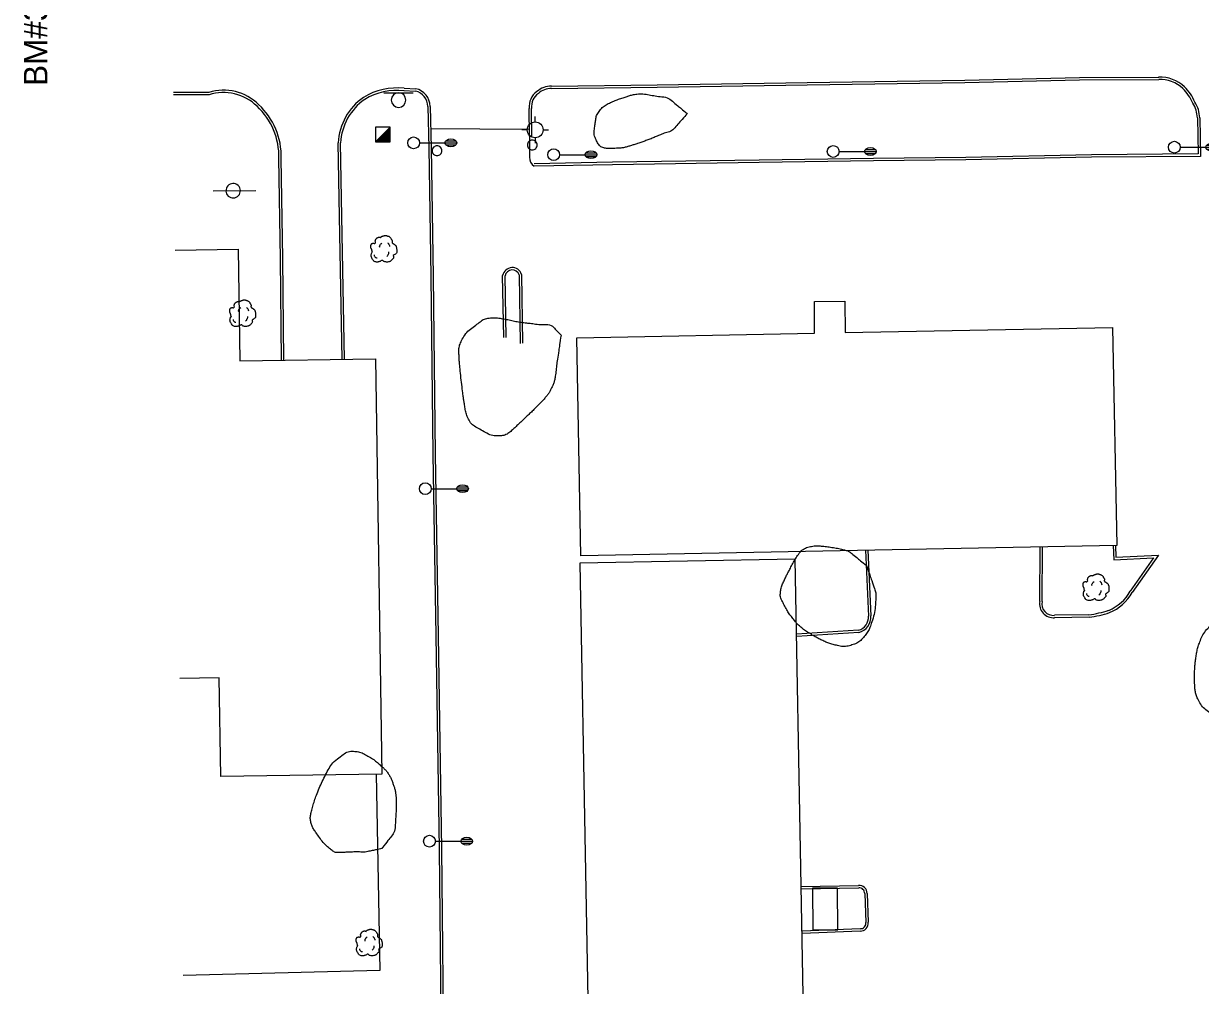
# Model space of a CAD drawing. Extents: x 2145380 to 2157287, y 139568 to 149130.
# Drawn here: x 2150211 to 2150511, y 140080.8 to 140325.9 of the extents above; entities that cross this region are included whole.
import ezdxf

# ---------------------------------------------------------------- set-up
doc = ezdxf.new("R2010")
doc.units = 0
for name, color, linetype in [('SURV_Benchmark', 7, 'Continuous'), ('TOPO_Asphalt', 7, 'Continuous'), ('TOPO_Building', 7, 'Continuous'), ('TOPO_Curb Back', 7, 'Continuous'), ('TOPO_Fence', 7, 'Continuous'), ('TOPO_Light Pole', 7, 'Continuous'), ('TOPO_Misc', 7, 'Continuous'), ('TOPO_Sign', 7, 'Continuous'), ('TOPO_Tree', 7, 'Continuous'), ('TOPO_Tree Line', 7, 'Continuous'), ('TOPO_Water Fire Hydrant', 7, 'Continuous')]:
    doc.layers.add(name, color=color, linetype=linetype)

# ---------------------------------------------------------------- blocks, each defined once
blk = doc.blocks.new('LP')
at = {"layer": 'TOPO_Light Pole'}
blk.add_line((3.81, 0), (20.32, 0), dxfattribs=at)
for points in [[(20.32, 0), (27.94, 0)], [(20.32, 0), (23.5, 0)], [(20.83, 1.27), (27.43, 1.27)], [(20.83, 1.27), (23.5, 1.27)], [(23.71, 1.27), (27.43, 1.27)], [(23.71, 0), (27.94, 0)], [(20.83, -1.27), (27.43, -1.27)], [(20.83, -1.27), (23.5, -1.27)], [(23.71, -1.27), (27.43, -1.27)]]:
    blk.add_lwpolyline(points, dxfattribs=at)
blk.add_circle((0, 0), 3.81, dxfattribs=at)
blk.add_ellipse((24.13, 0), major_axis=(3.81, 0), ratio=0.666667, dxfattribs=at)
blk = doc.blocks.new('FIRHYD')
at = {"layer": 'TOPO_Water Fire Hydrant'}
for p, q in [((0, 10.2), (0, 17.3)), ((10.2, 0), (17.3, 0)), ((-10.2, 0), (-17.3, 0)), ((0, -10.2), (0, -17.3))]:
    blk.add_line(p, q, dxfattribs=at)
blk.add_circle((0, 0), 10.2, dxfattribs=at)
blk = doc.blocks.new('POST')
at = {"layer": 'TOPO_Misc'}
for start, end in [(89.99996, 180.00004), (179.99996, 270.00004), (359.99996, 90.00004), (269.99996, 0.00004)]:
    blk.add_arc((-0.01, 0.03), 3.16, start, end, dxfattribs=at)
blk = doc.blocks.new('TREE')
at = {"layer": 'TOPO_Tree'}
for points in [[(-14.1, -0.4), (-14.2, 0.5), (-14.4, 1.4), (-14.6, 2.3), (-14.8, 3.2), (-15.5, 4), (-15.7, 4.9), (-15.8, 5.6), (-15.7, 6.3), (-15.7, 7), (-15.6, 7.9), (-15.7, 8.8), (-15.1, 9.7), (-14.6, 10.4), (-13.8, 10.5), (-13, 10.7), (-12.2, 11), (-11.1, 10), (-10.4, 10.7), (-9.4, 11.7), (-10.3, 13.3), (-9.8, 14.4), (-9.6, 15.1), (-9.3, 15.9), (-8.8, 16.5), (-8.2, 17.3), (-7.5, 17.7), (-6.7, 18.1), (-6.1, 18.4), (-5.6, 18.6), (-5.1, 18.7), (-4.5, 18.7), (-4, 18.5), (-3.5, 18.1)], [(-3.5, 17.6), (-3.1, 18.3), (-2.6, 18.8), (-1.9, 19.2), (-1, 19.7), (-0.2, 20), (0.7, 20.2), (1.6, 20.5), (2.5, 20.8), (3.4, 20.8), (4.1, 20.7), (4.8, 20.5), (5.5, 20.2), (6.4, 19.9), (7.3, 19.7), (8.2, 19.2), (9.4, 18.4), (10, 17.2), (10.8, 16), (11.2, 15.3), (11.6, 14.6), (11.9, 13.9), (12.2, 13.1), (11.4, 12), (11.9, 11.2), (12, 11), (12.2, 10.9), (12.4, 10.7), (12.9, 10.4), (13.5, 10), (14, 9.7), (14.7, 9.2), (15.4, 8.7), (16.1, 8.1), (16.7, 7.5), (16.9, 6.7), (17.1, 6), (17.6, 4.4), (17.7, 2.8), (17.7, 1.2), (17.7, -0.2), (17.8, -2.2), (16.6, -3), (15.5, -3.8), (14.3, -4.6), (13.2, -5.3)], [(13.2, -5.3), (13.3, -5.8), (13.4, -6.3), (13.4, -6.7), (13.8, -8.5), (12.2, -10), (10.8, -11.5), (10, -12.3), (9.1, -12.8), (8.2, -13.1), (6, -13.8), (3.3, -13.6), (1.3, -13.1), (0.5, -12.9), (-0.1, -11.4), (-0.8, -11.5), (-2, -11.6), (-3.3, -12.8), (-4.5, -13.1), (-6.1, -13.5), (-7.8, -14), (-9.3, -13.6), (-11.4, -13.1), (-12.8, -11.4), (-14.1, -9.4), (-15.3, -7.3), (-15.6, -5.1), (-15.1, -3), (-14.9, -1.9), (-13.9, -0.8), (-13.5, 0.1)], [(-4.2, 5.1), (-4.5, 6.1), (-4.3, 7.2), (-3.8, 8.2), (-3.3, 9.3), (-2.7, 10.3), (-1.6, 11)], [(5.9, 11.2), (6.5, 10.7), (7, 10.2), (7.4, 9.5), (7.9, 8.6), (8.3, 7.6), (8.5, 6.6)], [(-11.4, -4.5), (-11.5, -5.4), (-11, -6.3), (-10.1, -7.2), (-9.3, -8), (-8.5, -8.3), (-7.7, -8.1)], [(4.8, -6.3), (5.7, -5.7), (6.3, -4.9), (6.8, -3.9), (7.4, -2.8), (7.6, -1.7), (7.5, -0.6)]]:
    blk.add_open_spline(points, degree=3, dxfattribs=at)

msp = doc.modelspace()

# ---------------------------------------------------------------- linework, layer by layer
at = {"layer": 'TOPO_Asphalt'}
msp.add_line((2150339.92, 140298.91), (2150314.77, 140299.09), dxfattribs=at)
msp.add_lwpolyline([(2150339.93, 140297.22), (2150339.98, 140291.88)], dxfattribs=at)
msp.add_arc((2150342.36, 140291.66), 2.39, 174.7377, 239.9631, dxfattribs=at)
at = {"layer": 'TOPO_Building'}
msp.add_lwpolyline([(2150249.66, 140268.17), (2150265.72, 140268.42), (2150266.15, 140239.97), (2150300.71, 140240.49), (2150302.32, 140134.63), (2150261.27, 140134.01), (2150260.89, 140159.19), (2150250.83, 140159.04)], dxfattribs=at)
for points in [[(2150420.46, 140247.17), (2150488.6, 140248.49), (2150489.68, 140192.93), (2150353.06, 140190.28), (2150351.99, 140245.84), (2150412.61, 140247.05), (2150412.6, 140255.05), (2150420.34, 140255.19)], [(2150352.76, 140188.44), (2150355.67, 140031.04), (2150410.6, 140032.05), (2150407.69, 140189.46)]]:
    msp.add_lwpolyline(points, close=True, dxfattribs=at)
at = {"layer": 'TOPO_Curb Back'}
for points in [[(2150345.57, 140309.36), (2150372.54, 140309.69), (2150410.72, 140310.27), (2150450.92, 140310.9), (2150480.16, 140311.55), (2150500.35, 140311.68)], [(2150345.58, 140309.96), (2150372.53, 140310.29), (2150410.71, 140310.87), (2150450.91, 140311.5), (2150480.15, 140312.15), (2150500.34, 140312.28)], [(2150307.97, 140308.82), (2150310.91, 140308.72)], [(2150308.02, 140309.42), (2150310.99, 140309.32)], [(2150258.19, 140308.37), (2150249.26, 140308.36)], [(2150258.28, 140307.77), (2150249.26, 140307.76)], [(2150314.01, 140304.81), (2150314.31, 140294.26), (2150314.84, 140261.44), (2150315.34, 140216.16), (2150316.1, 140169.9), (2150316.95, 140115.57), (2150317.56, 140056.63), (2150318.47, 140015.75), (2150318.91, 139970.85), (2150319.59, 139936.26), (2150345.99, 139936.73), (2150379.22, 139937.18), (2150415.3, 139937.61), (2150440.34, 139938.14), (2150484.48, 139938.5), (2150535.71, 139939.38)], [(2150314.61, 140304.82), (2150314.91, 140294.28), (2150315.44, 140261.45), (2150315.94, 140216.16), (2150316.7, 140169.91), (2150317.55, 140115.57), (2150318.16, 140056.64), (2150319.07, 140015.76), (2150319.51, 139970.86), (2150320.18, 139936.88), (2150345.98, 139937.33), (2150379.21, 139937.78), (2150415.29, 139938.21), (2150440.33, 139938.74), (2150484.47, 139939.1), (2150535.7, 139939.98)], [(2150339.93, 140297.22), (2150339.91, 140304.27)], [(2150340.53, 140297.22), (2150340.51, 140304.31)], [(2150510.2, 140301.9), (2150510.38, 140292.68), (2150483.18, 140292.47), (2150451.16, 140291.79), (2150427.66, 140291.56), (2150398.49, 140291.13), (2150361.08, 140290.56), (2150341.16, 140290.19)], [(2150510.8, 140301.91), (2150510.99, 140292.08), (2150483.19, 140291.87), (2150451.17, 140291.19), (2150427.66, 140290.96), (2150398.49, 140290.53), (2150361.09, 140289.96), (2150341.17, 140289.59)], [(2150292.18, 140240.36), (2150291.52, 140276.74), (2150291.19, 140295.54)], [(2150292.78, 140240.37), (2150292.12, 140276.75), (2150291.79, 140295.53)], [(2150276.78, 140240.13), (2150276.51, 140266), (2150276.08, 140291.58)], [(2150277.38, 140240.14), (2150277.11, 140266.01), (2150276.68, 140291.58)], [(2150333.43, 140245.9), (2150333.12, 140261.7)], [(2150334.03, 140245.91), (2150333.72, 140261.65)], [(2150337.35, 140261.88), (2150337.57, 140244.42)], [(2150337.95, 140261.98), (2150338.17, 140244.43)], [(2150425.61, 140191.68), (2150426.35, 140174.93)], [(2150426.21, 140191.7), (2150426.95, 140174.96)], [(2150470.04, 140178.67), (2150470.14, 140192.55)], [(2150470.64, 140178.61), (2150470.74, 140192.55)], [(2150488.7, 140192.9), (2150488.89, 140189.28), (2150499.06, 140189.79), (2150493.09, 140181.24)], [(2150489.3, 140192.92), (2150489.46, 140189.91), (2150500.26, 140190.45), (2150493.6, 140180.91)], [(2150482.57, 140175.22), (2150473.79, 140175.11)], [(2150482.62, 140174.62), (2150473.82, 140174.51)], [(2150423.8, 140171.31), (2150408.05, 140170.33)], [(2150423.89, 140170.72), (2150408.07, 140169.73)], [(2150409.24, 140105.98), (2150423.85, 140106.23)], [(2150409.25, 140105.38), (2150423.88, 140105.63)], [(2150425.42, 140104.21), (2150425.72, 140096.83)], [(2150426.02, 140104.21), (2150426.32, 140096.88)], [(2150424.22, 140095.24), (2150409.44, 140094.65)], [(2150424.22, 140094.64), (2150409.46, 140094.05)]]:
    msp.add_lwpolyline(points, dxfattribs=at)
for centre, radius, start, end in [((2150500.64, 140303.08), 9.2, 47.0489, 91.8924), ((2150500.64, 140303.08), 8.6, 47.0942, 91.945), ((2150261.96, 140296.12), 12.82, 45.6383, 107.1027), ((2150306.22, 140293.01), 16.51, 83.7465, 121.3206), ((2150306.22, 140293.01), 15.9, 83.6638, 121.2508), ((2150310, 140304.82), 4.01, 359.8783, 76.7774), ((2150310, 140304.82), 4.61, 359.9966, 77.5444), ((2150344.43, 140304.82), 4.55, 124.552, 186.9825), ((2150345.36, 140304.85), 5.11, 87.5076, 133.3508), ((2150345.36, 140304.85), 4.51, 87.3018, 133.9373), ((2150498.7, 140301.38), 11.17, 22.2118, 45.7247), ((2150498.7, 140301.38), 11.77, 22.498, 45.7583), ((2150261.96, 140296.12), 12.22, 45.6006, 107.5207), ((2150306.39, 140294.65), 15.23, 125.0921, 176.6305), ((2150306.39, 140294.65), 14.63, 125.1695, 176.5425), ((2150344.43, 140304.82), 3.95, 123.8831, 187.4881), ((2150503.2, 140301.74), 7, 1.252, 33.4792), ((2150503.2, 140301.74), 7.6, 1.2467, 33.0291), ((2150258.65, 140292.05), 17.44, 358.4469, 47.1664), ((2150258.65, 140292.05), 18.04, 358.4888, 47.1406), ((2150335.57, 140261.24), 2.49, 17.2622, 169.5159), ((2150335.57, 140261.24), 1.89, 19.7264, 167.7946), ((2150483.21, 140186.84), 11.36, 292.8542, 330.4208), ((2150483.21, 140186.84), 11.96, 292.7186, 330.2842), ((2150473.52, 140178.03), 3.54, 169.5913, 274.9213), ((2150473.52, 140178.03), 2.94, 168.6189, 275.3328), ((2150422.94, 140174.63), 3.43, 284.4972, 4.8902), ((2150422.94, 140174.63), 4.03, 283.6482, 4.7077), ((2150477.86, 140207.34), 32.46, 278.3368, 287.4939), ((2150477.86, 140207.33), 33.06, 278.267, 287.5426), ((2150424.02, 140104.24), 2, 359.209, 94.9419), ((2150424.02, 140104.24), 1.4, 358.5992, 95.7188), ((2150424.29, 140096.67), 2.04, 267.9427, 5.8091), ((2150424.29, 140096.67), 1.44, 267.1207, 6.474)]:
    msp.add_arc(centre, radius, start, end, dxfattribs=at)
at = {"layer": 'TOPO_Fence'}
msp.add_lwpolyline([(2150300.84, 140134.61), (2150301.79, 140084.62), (2150251.66, 140083.33)], dxfattribs=at)
at = {"layer": 'TOPO_Misc'}
for p, q in [((2150300.72, 140295.79), (2150304.45, 140299.54)), ((2150301.62, 140296.7), (2150304.46, 140296.7)), ((2150301.81, 140296.89), (2150304.46, 140296.89)), ((2150302, 140297.08), (2150304.46, 140297.08)), ((2150302.18, 140297.26), (2150304.45, 140297.26)), ((2150302.37, 140297.45), (2150304.45, 140297.45)), ((2150302.56, 140297.64), (2150304.45, 140297.64)), ((2150302.74, 140297.82), (2150304.45, 140297.82)), ((2150302.93, 140298.01), (2150304.45, 140298.01)), ((2150303.11, 140298.19), (2150304.45, 140298.19)), ((2150303.3, 140298.38), (2150304.45, 140298.38)), ((2150303.48, 140298.57), (2150304.45, 140298.57)), ((2150303.68, 140298.76), (2150304.45, 140298.76)), ((2150303.87, 140298.95), (2150304.45, 140298.95)), ((2150304.05, 140299.13), (2150304.45, 140299.13)), ((2150304.24, 140299.32), (2150304.45, 140299.32)), ((2150304.42, 140299.5), (2150304.45, 140299.5)), ((2150300.87, 140295.95), (2150304.46, 140295.95)), ((2150301.06, 140296.14), (2150304.46, 140296.14)), ((2150301.24, 140296.33), (2150304.46, 140296.33)), ((2150301.43, 140296.52), (2150304.46, 140296.52))]:
    msp.add_line(p, q, dxfattribs=at)
msp.add_lwpolyline([(2150304.46, 140295.8), (2150304.45, 140299.54), (2150300.71, 140299.53), (2150300.72, 140295.79), (2150304.46, 140295.8)], dxfattribs=at)
at = {"layer": 'TOPO_Sign'}
for points in [[(2150302.83, 140308.3), (2150310.32, 140308.31)], [(2150304.71, 140306.43), (2150304.71, 140306.43)], [(2150306.58, 140308.3), (2150306.58, 140308.3)], [(2150308.44, 140306.43), (2150308.44, 140306.43)], [(2150306.58, 140304.56), (2150306.58, 140304.56)], [(2150259.29, 140283.29), (2150270.17, 140283.35)]]:
    msp.add_lwpolyline(points, dxfattribs=at)
msp.add_lwpolyline([(2150418.55, 140094.98), (2150418.49, 140105.57), (2150412.14, 140105.54), (2150412.2, 140094.95)], close=True, dxfattribs=at)
for centre, radius, start, end in [((2150306.58, 140306.43), 1.87, 90, 180), ((2150306.58, 140306.43), 1.87, 180, 270), ((2150306.58, 140306.43), 1.87, 360, 90), ((2150306.58, 140306.43), 1.87, 270, 0), ((2150264.43, 140283.32), 1.84, 47.4196, 227.4196), ((2150264.43, 140283.32), 1.84, 227.4196, 47.4196)]:
    msp.add_arc(centre, radius, start, end, dxfattribs=at)
at = {"layer": 'TOPO_Tree Line'}
for points in [[(2150380.16, 140302.97), (2150378.9, 140304.01), (2150377.65, 140305.06), (2150376.39, 140306.11), (2150375.11, 140307.18), (2150373.26, 140307.27), (2150371.61, 140307.56), (2150370.06, 140307.83), (2150368.47, 140308.12), (2150366.94, 140307.88), (2150365.98, 140307.73), (2150365.05, 140307.44), (2150364.12, 140307.13), (2150362.92, 140306.73), (2150361.77, 140306.3), (2150360.62, 140305.77), (2150359.47, 140305.25), (2150358.5, 140304.59), (2150357.69, 140303.48), (2150356.98, 140302.49), (2150356.85, 140301.42), (2150356.69, 140300.35), (2150356.49, 140299.01), (2150356.35, 140297.58), (2150356.97, 140296.23), (2150357.42, 140295.27), (2150358.14, 140294.42), (2150359.13, 140294.2), (2150359.98, 140294.01), (2150360.84, 140294.06), (2150361.7, 140294.12), (2150362.59, 140294.19), (2150363.5, 140294.17), (2150364.38, 140294.39), (2150365.28, 140294.63), (2150366.14, 140294.9), (2150367.01, 140295.2), (2150368.05, 140295.54), (2150369.09, 140295.89), (2150370.12, 140296.27), (2150371.21, 140296.67), (2150372.27, 140297.14), (2150373.34, 140297.59), (2150374.58, 140298.1), (2150376.07, 140298.34), (2150376.95, 140299.34), (2150378.02, 140300.55), (2150379.09, 140301.76), (2150380.16, 140302.97), (2150380.16, 140302.97)], [(2150348.01, 140246.51), (2150347.48, 140247.06), (2150346.95, 140247.61), (2150346.42, 140248.16), (2150345.24, 140249.4), (2150343.13, 140249.13), (2150341.44, 140249.36), (2150340.14, 140249.54), (2150338.83, 140249.64), (2150337.55, 140249.84), (2150336.15, 140250.06), (2150334.77, 140250.41), (2150333.37, 140250.65), (2150332.16, 140250.87), (2150330.9, 140251.01), (2150329.68, 140250.86), (2150328.43, 140250.71), (2150327.38, 140249.91), (2150326.31, 140249.1), (2150324.86, 140248), (2150323.65, 140247), (2150322.79, 140245.37), (2150322.2, 140244.25), (2150321.94, 140243.12), (2150321.98, 140241.95), (2150322.01, 140240.81), (2150322.07, 140239.67), (2150322.19, 140238.54), (2150322.44, 140236.23), (2150322.69, 140233.92), (2150322.98, 140231.61), (2150323.09, 140230.66), (2150323.25, 140229.72), (2150323.39, 140228.77), (2150323.58, 140227.54), (2150323.82, 140226.34), (2150324.39, 140225.17), (2150325.04, 140223.81), (2150326.28, 140223.12), (2150327.64, 140222.32), (2150329.1, 140221.46), (2150330.59, 140220.8), (2150332.05, 140220.83), (2150333.1, 140220.85), (2150334.28, 140221.24), (2150335.17, 140221.99), (2150336.03, 140222.72), (2150336.75, 140223.44), (2150337.53, 140224.18), (2150338.28, 140224.88), (2150339.03, 140225.58), (2150339.77, 140226.29), (2150340.66, 140227.13), (2150341.52, 140228), (2150342.38, 140228.87), (2150343.05, 140229.54), (2150343.69, 140230.23), (2150344.3, 140230.95), (2150344.85, 140231.6), (2150345.25, 140232.34), (2150345.61, 140233.11), (2150345.98, 140233.92), (2150346.33, 140234.74), (2150346.46, 140235.62), (2150346.7, 140237.2), (2150346.85, 140238.78), (2150347.08, 140240.35), (2150347.39, 140242.4), (2150347.7, 140244.46), (2150348.01, 140246.51)], [(2150425.86, 140187.8), (2150424.58, 140188.85), (2150423.3, 140189.89), (2150422.02, 140190.94), (2150421.34, 140191.49), (2150420.44, 140191.7), (2150419.58, 140191.92), (2150418.15, 140192.29), (2150416.71, 140192.48), (2150415.26, 140192.66), (2150414.05, 140192.81), (2150412.8, 140192.89), (2150411.58, 140192.62), (2150410.27, 140192.33), (2150409.07, 140191.49), (2150408.32, 140190.36), (2150407.55, 140189.2), (2150406.93, 140188.03), (2150406.3, 140186.83), (2150405.84, 140185.94), (2150405.4, 140185.1), (2150404.97, 140184.17), (2150404.48, 140183.13), (2150404.04, 140182.07), (2150403.94, 140181.01), (2150403.82, 140179.82), (2150404.42, 140178.62), (2150405.06, 140177.43), (2150405.69, 140176.23), (2150406.33, 140175.27), (2150407.13, 140174.27), (2150407.75, 140173.48), (2150408.37, 140172.72), (2150409.14, 140172.08), (2150410.06, 140171.31), (2150411.04, 140170.68), (2150412.07, 140170.07), (2150413.02, 140169.51), (2150413.97, 140169.02), (2150414.97, 140168.54), (2150416, 140168.06), (2150417.07, 140167.75), (2150418.14, 140167.47), (2150419.43, 140167.13), (2150420.86, 140167.14), (2150422.17, 140167.56), (2150423.4, 140167.95), (2150424.4, 140168.66), (2150425.28, 140169.7), (2150426.13, 140170.71), (2150426.66, 140171.71), (2150427.05, 140172.9), (2150427.7, 140174.85), (2150428.12, 140176.81), (2150428.2, 140178.79), (2150428.24, 140179.79), (2150428.27, 140180.86), (2150427.94, 140181.81), (2150427.25, 140183.81), (2150426.56, 140185.81), (2150425.86, 140187.8)], [(2150529.79, 140180.19), (2150527.76, 140179.6), (2150525.73, 140179.02), (2150523.7, 140178.43), (2150522.69, 140178.13), (2150521.78, 140177.59), (2150520.83, 140177.12), (2150519.11, 140176.26), (2150517.45, 140175.34), (2150515.79, 140174.34), (2150514.9, 140173.81), (2150514.14, 140173.15), (2150513.41, 140172.38), (2150512.27, 140171.17), (2150511.39, 140169.84), (2150510.82, 140168.3), (2150510.39, 140167.18), (2150510.11, 140166.05), (2150509.92, 140164.88), (2150509.74, 140163.72), (2150509.6, 140162.57), (2150509.52, 140161.41), (2150509.41, 140159.81), (2150509.46, 140158.21), (2150509.58, 140156.61), (2150509.66, 140155.57), (2150509.93, 140154.59), (2150510.43, 140153.61), (2150511.22, 140152.06), (2150512.33, 140150.96), (2150513.79, 140149.98), (2150514.54, 140149.48), (2150515.29, 140149.09), (2150516.13, 140149.02), (2150517.62, 140148.9), (2150519.11, 140148.86), (2150520.6, 140148.88), (2150522.59, 140148.92), (2150524.59, 140148.83), (2150526.58, 140149.07), (2150527.52, 140149.19), (2150528.45, 140149.32), (2150529.39, 140149.46), (2150530.74, 140149.65), (2150532.09, 140149.84), (2150533.44, 140150.05), (2150534.6, 140150.23), (2150535.67, 140150.71), (2150536.76, 140151.17), (2150537.9, 140151.65), (2150538.95, 140152.23), (2150539.97, 140152.95), (2150541.39, 140153.94), (2150542.5, 140155.11), (2150543.54, 140156.54), (2150544.1, 140157.31), (2150544.49, 140158.11), (2150544.73, 140159.01), (2150545.13, 140160.45), (2150545.24, 140161.93), (2150545.14, 140163.37), (2150545.06, 140164.35), (2150544.96, 140165.36), (2150544.53, 140166.31), (2150544.12, 140167.21), (2150543.67, 140168.02), (2150543.2, 140168.86), (2150542.04, 140170.9), (2150540.86, 140172.9), (2150539.63, 140174.91), (2150539.03, 140175.9), (2150538.5, 140177.06), (2150537.44, 140177.6), (2150536.31, 140178.18), (2150535.13, 140178.49), (2150533.95, 140178.86), (2150532.56, 140179.31), (2150531.18, 140179.75), (2150529.79, 140180.19)], [(2150302.31, 140115.66), (2150303.13, 140116.72), (2150303.95, 140117.78), (2150304.78, 140118.84), (2150305.72, 140120.05), (2150305.73, 140121.79), (2150305.84, 140123.33), (2150305.94, 140124.69), (2150305.99, 140126.05), (2150305.97, 140127.42), (2150305.96, 140128.26), (2150305.92, 140129.1), (2150305.8, 140129.94), (2150305.67, 140130.8), (2150305.39, 140131.6), (2150305.09, 140132.42), (2150304.77, 140133.27), (2150304.42, 140134.08), (2150303.9, 140134.84), (2150303.41, 140135.57), (2150302.81, 140136.15), (2150302.16, 140136.74), (2150301.2, 140137.61), (2150300.29, 140138.32), (2150299.1, 140139.04), (2150297.89, 140139.77), (2150296.66, 140140.31), (2150295.44, 140140.43), (2150294.1, 140140.55), (2150292.76, 140139.88), (2150291.43, 140138.85), (2150289.73, 140137.51), (2150288.86, 140136.15), (2150288, 140134.49), (2150287.12, 140132.76), (2150286.35, 140131.05), (2150285.66, 140129.24), (2150285.13, 140127.87), (2150284.71, 140126.49), (2150284.36, 140125.08), (2150284.11, 140124.11), (2150284.05, 140123.03), (2150284.34, 140122.06), (2150284.62, 140121.11), (2150285.14, 140120.3), (2150285.72, 140119.47), (2150286.66, 140118.11), (2150287.53, 140116.94), (2150288.84, 140115.84), (2150289.62, 140115.18), (2150290.48, 140114.6), (2150291.44, 140114.64), (2150292.57, 140114.68), (2150293.7, 140114.73), (2150294.83, 140114.78), (2150296.25, 140114.85), (2150297.7, 140114.68), (2150299.09, 140114.97), (2150300.16, 140115.2), (2150301.23, 140115.43), (2150302.31, 140115.66), (2150302.31, 140115.66)]]:
    msp.add_open_spline(points, degree=3, dxfattribs=at)

# ---------------------------------------------------------------- block references
at = {"layer": 'TOPO_Light Pole', "xscale": 0.39370000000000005, "yscale": 0.3937000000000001}
for p in [(2150310.42, 140295.52), (2150346.13, 140292.5), (2150417.37, 140293.32), (2150504.34, 140294.41), (2150313.4, 140207.38), (2150314.47, 140117.54)]:
    msp.add_blockref('LP', p, dxfattribs=at)
at = {"layer": 'TOPO_Misc', "xscale": 0.39370000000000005, "yscale": 0.3937000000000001}
for p in [(2150316.4, 140293.5), (2150340.67, 140294.97)]:
    msp.add_blockref('POST', p, dxfattribs=at)
at = {"layer": 'TOPO_Tree', "xscale": 0.19685000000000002, "yscale": 0.19685000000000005}
for p in [(2150302.63, 140267.83), (2150266.66, 140251.41), (2150484.18, 140181.58), (2150298.9, 140091.02)]:
    msp.add_blockref('TREE', p, dxfattribs=at)
at = {"layer": 'TOPO_Water Fire Hydrant', "xscale": 0.19685000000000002, "yscale": 0.19685000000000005}
msp.add_blockref('FIRHYD', (2150341.41, 140298.84), dxfattribs=at)

# ---------------------------------------------------------------- texts
at = {"layer": 'SURV_Benchmark'}
msp.add_text('BM#33', height=6, rotation=90, dxfattribs=at).set_placement((2150217.08, 140310.04))

doc.saveas('drawing.dxf')
